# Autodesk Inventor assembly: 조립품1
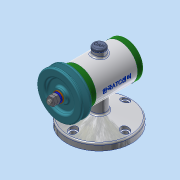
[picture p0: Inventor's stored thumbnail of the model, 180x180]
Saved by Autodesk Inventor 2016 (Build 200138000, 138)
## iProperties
Created: 2018-12
Part Number: 조립품1
Material: 일반
Document SubType Name: Assembly
Designer: 3sil_cad018
Author: 3sil_cad018
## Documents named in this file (15)
- C:\Users\3sil_cad018\Desktop\481207V1002\조립품1.iam
- C:\Users\3sil_cad018\Desktop\481207V1002\본체.ipt
- C:\Users\3sil_cad018\Desktop\481207V1002\V벨트풀리.ipt
- C:\Users\3sil_cad018\Desktop\481207V1002\고무캡.ipt
- C:\Users\3sil_cad018\Desktop\481207V1002\뒤커버.ipt
- C:\Users\3sil_cad018\Desktop\481207V1002\베어링 15 x 32 x 9.ipt
- C:\Users\3sil_cad018\Desktop\481207V1002\볼트 M4 x 12.ipt
- C:\Users\3sil_cad018\Desktop\481207V1002\스프링와셔 8.ipt
- C:\Users\3sil_cad018\Desktop\481207V1002\앞커버.ipt
- C:\Users\3sil_cad018\Desktop\481207V1002\오일 실 15 25 7.ipt
- C:\Users\3sil_cad018\Desktop\481207V1002\축.ipt
- C:\Users\3sil_cad018\Desktop\481207V1002\키 3 x 3 x 12.ipt
- C:\Users\3sil_cad018\Desktop\481207V1002\와셔 8x17.ipt
- C:\Users\3sil_cad018\Desktop\481207V1002\너트 M8.ipt
- 너트 M8.ipt
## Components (2 placed, 2 different names)
1. V벨트풀리:1 — 각도:3
2. 고무캡:1
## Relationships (1: Angle 1)
- 각도:3 [Angle]: V벨트풀리:1
